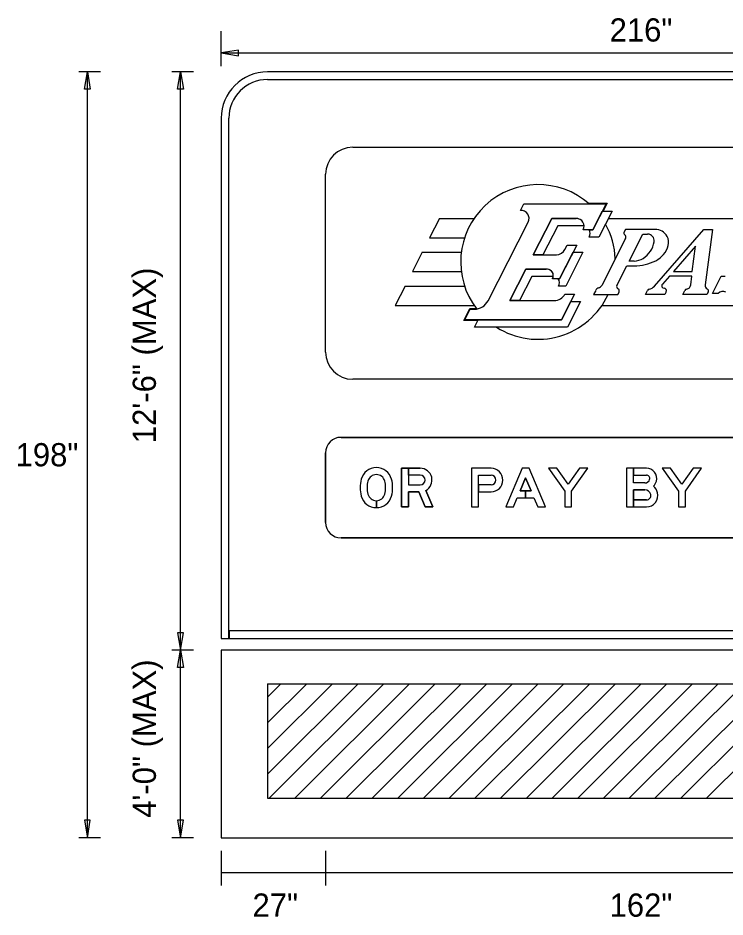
# Model space of a CAD drawing. Extents: x 10268312 to 10268706, y 2142548 to 2142786.
# Drawn here: x 10268663.93 to 10268686.56, y 2142607.93 to 2142636.7 of the extents above; entities that cross this region are included whole.
import ezdxf

# ---------------------------------------------------------------- set-up
doc = ezdxf.new("R2010")
doc.units = 0
for name, color, linetype in [('GSBWFill', 7, 'Continuous'), ('GSDims', 7, 'Continuous'), ('SignPanel', 7, 'Continuous'), ('TextMisc', 7, 'Continuous')]:
    doc.layers.add(name, color=color, linetype=linetype)

msp = doc.modelspace()

# ---------------------------------------------------------------- linework, layer by layer
at = {"layer": 'GSBWFill'}
for p, q in [((10268670.431, 2142635.162), (10268670.431, 2142636.276)), ((10268695.683, 2142634.977), (10268671.916, 2142634.977)), ((10268671.916, 2142634.73), (10268695.683, 2142634.73)), ((10268674.27, 2142623.279), (10268693.329, 2142623.279)), ((10268674.27, 2142623.279), (10268693.329, 2142623.279)), ((10268673.775, 2142620.556), (10268673.775, 2142622.784)), ((10268673.775, 2142620.556), (10268673.775, 2142622.784)), ((10268693.329, 2142620.061), (10268674.27, 2142620.061)), ((10268693.329, 2142620.061), (10268674.27, 2142620.061))]:
    msp.add_line(p, q, dxfattribs=at)
for points in [[(10268670.431, 2142633.492), (10268670.431, 2142616.842), (10268670.678, 2142616.842), (10268670.678, 2142633.492)], [(10268696.921, 2142617.09), (10268670.686, 2142617.09), (10268670.686, 2142616.842), (10268697.169, 2142616.842), (10268697.169, 2142616.842), (10268697.169, 2142633.492)]]:
    msp.add_lwpolyline(points, dxfattribs=at)
for centre, radius, start, end in [((10268671.916, 2142633.492), 1.485, 90, 180), ((10268671.916, 2142633.492), 1.238, 90, 180), ((10268674.27, 2142622.784), 0.495, 90, 180), ((10268674.27, 2142622.784), 0.495, 90, 180), ((10268674.27, 2142620.556), 0.495, 180, 270), ((10268674.27, 2142620.556), 0.495, 180, 270)]:
    msp.add_arc(centre, radius, start, end, dxfattribs=at)
at = {"layer": 'GSDims'}
for p, q in [((10268670.431, 2142635.58), (10268697.169, 2142635.58)), ((10268666.567, 2142634.977), (10268665.871, 2142634.977)), ((10268666.149, 2142610.467), (10268666.149, 2142634.977)), ((10268669.548, 2142634.977), (10268668.852, 2142634.977)), ((10268669.13, 2142616.471), (10268669.13, 2142634.977)), ((10268669.548, 2142616.471), (10268668.852, 2142616.471)), ((10268669.13, 2142610.467), (10268669.13, 2142616.471)), ((10268666.567, 2142610.467), (10268665.871, 2142610.467)), ((10268669.548, 2142610.467), (10268668.852, 2142610.467)), ((10268670.431, 2142610.05), (10268670.431, 2142608.936)), ((10268673.773, 2142610.05), (10268673.773, 2142608.936)), ((10268670.431, 2142609.353), (10268673.773, 2142609.353)), ((10268673.773, 2142609.353), (10268693.826, 2142609.353))]:
    msp.add_line(p, q, dxfattribs=at)
for points in [[(10268670.431, 2142635.58), (10268670.988, 2142635.487), (10268670.988, 2142635.672)], [(10268666.149, 2142634.977), (10268666.242, 2142634.42), (10268666.057, 2142634.42)], [(10268669.13, 2142634.977), (10268669.223, 2142634.42), (10268669.037, 2142634.42)], [(10268669.13, 2142616.471), (10268669.223, 2142617.028), (10268669.037, 2142617.028)], [(10268669.13, 2142616.471), (10268669.223, 2142615.914), (10268669.037, 2142615.914)], [(10268666.149, 2142610.467), (10268666.242, 2142611.024), (10268666.057, 2142611.024)], [(10268669.13, 2142610.467), (10268669.223, 2142611.024), (10268669.037, 2142611.024)]]:
    msp.add_lwpolyline(points, close=True, dxfattribs=at)
at = {"layer": 'SignPanel'}
for p, q in [((10268674.642, 2142632.563), (10268692.958, 2142632.563)), ((10268673.775, 2142626.004), (10268673.775, 2142631.697)), ((10268680.016, 2142630.54), (10268680.122, 2142630.748)), ((10268680.122, 2142630.748), (10268682.752, 2142630.748)), ((10268682.186, 2142630.771), (10268682.789, 2142630.771)), ((10268682.752, 2142630.748), (10268682.33, 2142629.92)), ((10268682.789, 2142630.771), (10268682.659, 2142630.516)), ((10268677.42, 2142630.283), (10268677.105, 2142629.665)), ((10268677.42, 2142630.283), (10268678.53, 2142630.283)), ((10268681.013, 2142630.283), (10268680.422, 2142629.123)), ((10268680.422, 2142629.123), (10268681.013, 2142630.283)), ((10268681.801, 2142630.283), (10268681.013, 2142630.283)), ((10268681.013, 2142630.283), (10268681.801, 2142630.283)), ((10268682.33, 2142629.92), (10268682.633, 2142630.516)), ((10268682.946, 2142630.516), (10268682.524, 2142629.688)), ((10268682.633, 2142630.516), (10268682.946, 2142630.516)), ((10268682.827, 2142630.283), (10268691.652, 2142630.283)), ((10268678.977, 2142627.65), (10268680.261, 2142630.17)), ((10268681.207, 2142630.052), (10268680.734, 2142629.123)), ((10268682.049, 2142630.052), (10268681.207, 2142630.052)), ((10268682.33, 2142629.92), (10268682.021, 2142629.92)), ((10268682.215, 2142629.92), (10268682.33, 2142629.92)), ((10268682.524, 2142629.688), (10268682.215, 2142629.688)), ((10268683.376, 2142629.935), (10268683.334, 2142629.853)), ((10268684.323, 2142629.935), (10268683.376, 2142629.935)), ((10268683.497, 2142628.922), (10268683.935, 2142629.78)), ((10268683.497, 2142628.922), (10268683.935, 2142629.78)), ((10268683.935, 2142629.78), (10268684.084, 2142629.78)), ((10268683.935, 2142629.78), (10268684.084, 2142629.78)), ((10268684.3, 2142628.119), (10268685.879, 2142629.935)), ((10268685.879, 2142629.935), (10268686.158, 2142629.935)), ((10268686.158, 2142629.935), (10268685.926, 2142628.155)), ((10268677.105, 2142629.665), (10268678.225, 2142629.665)), ((10268681.819, 2142629.433), (10268681.267, 2142628.35)), ((10268681.437, 2142629.292), (10268681.509, 2142629.433)), ((10268681.509, 2142629.433), (10268681.819, 2142629.433)), ((10268683.379, 2142629.643), (10268682.613, 2142628.14)), ((10268685.62, 2142629.402), (10268684.914, 2142628.589)), ((10268685.62, 2142629.402), (10268684.914, 2142628.589)), ((10268685.515, 2142628.589), (10268685.62, 2142629.402)), ((10268685.515, 2142628.589), (10268685.62, 2142629.402)), ((10268676.869, 2142629.201), (10268676.554, 2142628.582)), ((10268676.869, 2142629.201), (10268678.12, 2142629.201)), ((10268680.422, 2142629.123), (10268681.162, 2142629.123)), ((10268680.734, 2142629.123), (10268680.422, 2142629.123)), ((10268681.267, 2142628.35), (10268681.7, 2142629.201)), ((10268682.013, 2142629.201), (10268681.461, 2142628.118)), ((10268681.7, 2142629.201), (10268682.013, 2142629.201)), ((10268683.65, 2142628.922), (10268683.497, 2142628.922)), ((10268683.65, 2142628.922), (10268683.497, 2142628.922)), ((10268676.554, 2142628.582), (10268678.12, 2142628.582)), ((10268680.186, 2142628.659), (10268679.673, 2142627.654)), ((10268679.673, 2142627.654), (10268680.186, 2142628.659)), ((10268680.865, 2142628.659), (10268680.186, 2142628.659)), ((10268680.186, 2142628.659), (10268680.835, 2142628.657)), ((10268683.098, 2142628.14), (10268683.418, 2142628.767)), ((10268683.418, 2142628.767), (10268683.65, 2142628.767)), ((10268684.914, 2142628.589), (10268685.515, 2142628.589)), ((10268684.914, 2142628.589), (10268685.515, 2142628.589)), ((10268680.38, 2142628.427), (10268679.986, 2142627.654)), ((10268681.062, 2142628.424), (10268680.38, 2142628.427)), ((10268681.267, 2142628.35), (10268681.034, 2142628.35)), ((10268681.218, 2142628.35), (10268681.267, 2142628.35)), ((10268684.78, 2142628.434), (10268684.556, 2142628.177)), ((10268685.499, 2142628.434), (10268684.78, 2142628.434)), ((10268685.462, 2142628.155), (10268685.499, 2142628.434)), ((10268686.157, 2142627.886), (10268686.437, 2142628.437)), ((10268686.437, 2142628.437), (10268686.562, 2142628.437)), ((10268676.318, 2142628.118), (10268676.003, 2142627.499)), ((10268676.318, 2142628.118), (10268678.225, 2142628.118)), ((10268681.461, 2142628.118), (10268681.229, 2142628.118)), ((10268682.425, 2142627.983), (10268682.355, 2142627.847)), ((10268684.015, 2142627.847), (10268684.082, 2142627.979)), ((10268685.209, 2142627.847), (10268685.277, 2142627.981)), ((10268681.745, 2142627.862), (10268681.324, 2142627.035)), ((10268681.436, 2142627.862), (10268681.745, 2142627.862)), ((10268682.355, 2142627.847), (10268683.129, 2142627.847)), ((10268683.129, 2142627.847), (10268683.17, 2142627.93)), ((10268684.634, 2142627.847), (10268684.015, 2142627.847)), ((10268684.679, 2142627.936), (10268684.634, 2142627.847)), ((10268685.982, 2142627.847), (10268685.209, 2142627.847)), ((10268686.023, 2142627.927), (10268685.982, 2142627.847)), ((10268686.344, 2142627.886), (10268686.157, 2142627.886)), ((10268676.003, 2142627.499), (10268678.53, 2142627.499)), ((10268678.197, 2142627.015), (10268678.393, 2142627.4)), ((10268678.23, 2142627.035), (10268678.406, 2142627.379)), ((10268678.393, 2142627.4), (10268678.535, 2142627.4)), ((10268678.406, 2142627.379), (10268678.535, 2142627.379)), ((10268679.673, 2142627.654), (10268681.093, 2142627.654)), ((10268679.986, 2142627.654), (10268679.673, 2142627.654)), ((10268681.324, 2142627.035), (10268681.627, 2142627.63)), ((10268681.94, 2142627.63), (10268681.518, 2142626.803)), ((10268681.627, 2142627.63), (10268681.94, 2142627.63)), ((10268682.622, 2142627.499), (10268690.233, 2142627.499)), ((10268678.647, 2142627.015), (10268678.197, 2142627.015)), ((10268681.324, 2142627.035), (10268678.23, 2142627.035)), ((10268678.54, 2142626.803), (10268678.658, 2142627.035)), ((10268678.658, 2142627.035), (10268681.324, 2142627.035)), ((10268681.518, 2142626.803), (10268678.54, 2142626.803)), ((10268692.958, 2142625.138), (10268674.642, 2142625.138)), ((10268693.329, 2142623.279), (10268674.27, 2142623.279)), ((10268673.775, 2142622.784), (10268673.775, 2142620.556)), ((10268678.669, 2142622.066), (10268679.071, 2142622.066)), ((10268678.669, 2142622.066), (10268679.071, 2142622.066)), ((10268678.669, 2142622.066), (10268679.071, 2142622.066)), ((10268678.669, 2142621.534), (10268679.071, 2142621.534)), ((10268675.401, 2142621.03), (10268675.401, 2142621.252)), ((10268675.401, 2142621.252), (10268675.401, 2142621.03)), ((10268675.401, 2142621.03), (10268675.401, 2142621.252)), ((10268675.401, 2142621.252), (10268675.401, 2142621.03)), ((10268683.41, 2142621.051), (10268684.047, 2142621.051)), ((10268674.27, 2142620.061), (10268693.324, 2142620.061)), ((10268697.169, 2142616.471), (10268670.431, 2142616.471)), ((10268670.431, 2142616.471), (10268670.431, 2142610.467)), ((10268670.431, 2142610.467), (10268697.169, 2142610.467))]:
    msp.add_line(p, q, dxfattribs=at)
for points in [[(10268676.804, 2142622.289), (10268676.205, 2142622.289), (10268676.205, 2142621.051), (10268676.428, 2142621.051), (10268676.428, 2142621.534), (10268676.756, 2142621.534), (10268676.965, 2142621.051), (10268677.208, 2142621.051), (10268676.98, 2142621.578)], [(10268676.98, 2142621.578), (10268677.208, 2142621.051), (10268676.965, 2142621.051), (10268676.756, 2142621.534), (10268676.428, 2142621.534), (10268676.428, 2142621.051), (10268676.205, 2142621.051), (10268676.205, 2142622.289), (10268676.428, 2142622.289), (10268676.428, 2142621.757), (10268676.804, 2142621.757)], [(10268676.98, 2142621.578), (10268677.208, 2142621.051), (10268676.965, 2142621.051), (10268676.756, 2142621.534), (10268676.428, 2142621.534), (10268676.428, 2142621.051), (10268676.205, 2142621.051), (10268676.205, 2142622.289), (10268676.428, 2142622.289), (10268676.428, 2142621.757), (10268676.804, 2142621.757)], [(10268676.428, 2142622.066), (10268676.428, 2142622.289), (10268676.804, 2142622.289)], [(10268676.428, 2142622.066), (10268676.428, 2142622.289), (10268676.804, 2142622.289)], [(10268679.071, 2142622.289), (10268678.446, 2142622.289), (10268678.446, 2142621.051), (10268678.669, 2142621.051), (10268678.669, 2142621.534)], [(10268679.071, 2142622.289), (10268678.446, 2142622.289), (10268678.446, 2142621.051), (10268678.669, 2142621.051), (10268678.669, 2142622.066)], [(10268679.071, 2142622.289), (10268678.446, 2142622.289), (10268678.446, 2142621.051), (10268678.669, 2142621.051), (10268678.669, 2142622.066)], [(10268684.047, 2142622.289), (10268683.41, 2142622.289), (10268683.41, 2142621.051)], [(10268683.999, 2142621.819), (10268683.632, 2142621.819), (10268683.632, 2142622.289), (10268683.41, 2142622.289), (10268683.41, 2142621.051), (10268683.632, 2142621.051)], [(10268683.999, 2142621.819), (10268683.632, 2142621.819), (10268683.632, 2142622.289), (10268683.41, 2142622.289), (10268683.41, 2142621.051), (10268683.632, 2142621.051)], [(10268684.047, 2142622.289), (10268683.633, 2142622.289), (10268683.633, 2142622.066), (10268684.047, 2142622.066)], [(10268684.047, 2142622.289), (10268683.633, 2142622.289), (10268683.633, 2142622.066), (10268684.047, 2142622.066)], [(10268676.804, 2142622.066), (10268676.428, 2142622.066), (10268676.428, 2142621.757), (10268676.804, 2142621.757)], [(10268676.804, 2142622.066), (10268676.428, 2142622.066)], [(10268676.804, 2142622.066), (10268676.428, 2142622.066)], [(10268679.071, 2142621.757), (10268678.669, 2142621.757), (10268678.669, 2142622.066)], [(10268683.999, 2142621.819), (10268683.632, 2142621.819), (10268683.632, 2142622.066), (10268684.047, 2142622.066)], [(10268679.071, 2142621.757), (10268678.669, 2142621.757), (10268678.669, 2142621.534), (10268679.071, 2142621.534)], [(10268679.071, 2142621.757), (10268678.669, 2142621.757), (10268678.669, 2142621.534), (10268679.071, 2142621.534)], [(10268683.999, 2142621.596), (10268683.632, 2142621.596), (10268683.632, 2142621.274), (10268684.047, 2142621.274)], [(10268683.632, 2142621.051), (10268683.632, 2142621.596), (10268683.999, 2142621.596)], [(10268683.632, 2142621.051), (10268683.632, 2142621.596), (10268683.999, 2142621.596)], [(10268684.047, 2142621.274), (10268683.633, 2142621.274), (10268683.633, 2142621.051), (10268684.047, 2142621.051)], [(10268684.047, 2142621.274), (10268683.633, 2142621.274), (10268683.633, 2142621.051), (10268684.047, 2142621.051)]]:
    msp.add_lwpolyline(points, dxfattribs=at)
for points in [[(10268679.911, 2142621.342), (10268680.446, 2142621.342), (10268680.569, 2142621.051), (10268680.81, 2142621.051), (10268680.29, 2142622.289), (10268680.067, 2142622.289), (10268679.548, 2142621.051), (10268679.789, 2142621.051)], [(10268680.353, 2142621.565), (10268680.179, 2142621.565), (10268680.179, 2142621.342), (10268680.446, 2142621.342), (10268680.569, 2142621.051), (10268680.81, 2142621.051), (10268680.29, 2142622.289), (10268680.067, 2142622.289), (10268679.548, 2142621.051), (10268679.789, 2142621.051), (10268679.911, 2142621.342), (10268680.179, 2142621.342), (10268680.179, 2142621.565), (10268680.005, 2142621.565), (10268680.179, 2142621.979)], [(10268680.353, 2142621.565), (10268680.179, 2142621.565), (10268680.179, 2142621.342), (10268680.446, 2142621.342), (10268680.569, 2142621.051), (10268680.81, 2142621.051), (10268680.29, 2142622.289), (10268680.067, 2142622.289), (10268679.548, 2142621.051), (10268679.789, 2142621.051), (10268679.911, 2142621.342), (10268680.179, 2142621.342), (10268680.179, 2142621.565), (10268680.005, 2142621.565), (10268680.179, 2142621.979)], [(10268681.652, 2142621.553), (10268682.172, 2142622.289), (10268681.899, 2142622.289), (10268681.541, 2142621.781), (10268681.182, 2142622.289), (10268680.909, 2142622.289), (10268681.429, 2142621.553), (10268681.429, 2142621.051), (10268681.652, 2142621.051)], [(10268681.652, 2142621.553), (10268682.172, 2142622.289), (10268681.899, 2142622.289), (10268681.541, 2142621.781), (10268681.182, 2142622.289), (10268680.909, 2142622.289), (10268681.429, 2142621.553), (10268681.429, 2142621.051), (10268681.652, 2142621.051)], [(10268681.652, 2142621.553), (10268682.172, 2142622.289), (10268681.899, 2142622.289), (10268681.541, 2142621.781), (10268681.182, 2142622.289), (10268680.909, 2142622.289), (10268681.429, 2142621.553), (10268681.429, 2142621.051), (10268681.652, 2142621.051)], [(10268685.291, 2142621.553), (10268685.811, 2142622.289), (10268685.538, 2142622.289), (10268685.18, 2142621.781), (10268684.821, 2142622.289), (10268684.549, 2142622.289), (10268685.068, 2142621.553), (10268685.068, 2142621.051), (10268685.291, 2142621.051)], [(10268685.291, 2142621.553), (10268685.811, 2142622.289), (10268685.538, 2142622.289), (10268685.18, 2142621.781), (10268684.821, 2142622.289), (10268684.549, 2142622.289), (10268685.068, 2142621.553), (10268685.068, 2142621.051), (10268685.291, 2142621.051)], [(10268685.291, 2142621.553), (10268685.811, 2142622.289), (10268685.538, 2142622.289), (10268685.18, 2142621.781), (10268684.821, 2142622.289), (10268684.549, 2142622.289), (10268685.068, 2142621.553), (10268685.068, 2142621.051), (10268685.291, 2142621.051)], [(10268680.353, 2142621.565), (10268680.179, 2142621.979), (10268680.005, 2142621.565)]]:
    msp.add_lwpolyline(points, close=True, dxfattribs=at)
for centre, radius, start, end in [((10268674.642, 2142631.697), 0.866, 90, 180), ((10268680.576, 2142628.891), 2.475, 48.5904, 217.4727), ((10268680.033, 2142630.285), 0.255, 332.9998, 93.8045), ((10268681.802, 2142630.036), 0.248, 332.2089, 90), ((10268681.802, 2142630.036), 0.248, 3.5833, 90), ((10268680.576, 2142628.891), 2.475, 2.4236, 29.2771), ((10268681.996, 2142629.804), 0.248, 332.2089, 27.9127), ((10268683.402, 2142629.818), 0.0773, 152.9784, 231.1602), ((10268683.296, 2142629.685), 0.0928, 333.0027, 51.1602), ((10268684.084, 2142629.572), 0.209, 351.076, 90), ((10268684.084, 2142629.572), 0.209, 351.076, 90), ((10268684.323, 2142629.494), 0.441, 29.4315, 90), ((10268684.37, 2142629.521), 0.387, 344.7074, 29.4315), ((10268683.526, 2142629.659), 0.773, 302.4206, 351.076), ((10268683.526, 2142629.659), 0.773, 302.4206, 351.076), ((10268683.997, 2142629.623), 0.773, 296.6431, 344.7074), ((10268681.162, 2142629.432), 0.309, 270, 332.9883), ((10268683.65, 2142629.463), 0.541, 270, 302.4206), ((10268683.65, 2142629.463), 0.541, 270, 302.4206), ((10268683.65, 2142630.314), 1.547, 270, 296.6431), ((10268680.864, 2142628.458), 0.201, 350.3502, 98.3344), ((10268680.864, 2142628.458), 0.201, 327.421, 90), ((10268681.06, 2142628.226), 0.201, 327.421, 37.9799), ((10268682.562, 2142627.913), 0.155, 106.4317, 152.9742), ((10268682.475, 2142628.21), 0.155, 286.4317, 332.9959), ((10268683.167, 2142628.105), 0.0773, 152.9884, 244.7832), ((10268683.101, 2142627.965), 0.0773, 333.0239, 64.7832), ((10268684.151, 2142627.944), 0.0773, 102.7162, 153.0239), ((10268684.066, 2142628.321), 0.309, 282.7162, 318.9966), ((10268684.614, 2142628.126), 0.0773, 138.9824, 268.6869), ((10268684.61, 2142627.971), 0.0773, 332.9784, 88.6869), ((10268685.346, 2142627.946), 0.0773, 99.2397, 153.0239), ((10268685.309, 2142628.175), 0.155, 279.2397, 352.5632), ((10268686.049, 2142628.139), 0.124, 172.5884, 241.8673), ((10268685.954, 2142627.962), 0.0773, 332.9784, 61.8673), ((10268680.576, 2142628.891), 2.475, 237.5383, 335.047), ((10268681.093, 2142628.04), 0.387, 270, 332.5096), ((10268686.493, 2142627.728), 0.217, 64.3795, 133.1892), ((10268678.536, 2142627.874), 0.495, 270, 332.9991), ((10268678.536, 2142627.874), 0.475, 270, 277.5038), ((10268674.642, 2142626.004), 0.866, 180, 270), ((10268674.27, 2142622.784), 0.495, 90, 180), ((10268675.401, 2142621.809), 0.502, 14.9618, 165.0382), ((10268675.401, 2142621.809), 0.502, 14.9618, 165.0382), ((10268675.401, 2142621.809), 0.502, 14.9618, 165.0382), ((10268676.804, 2142621.911), 0.378, 297.837, 90), ((10268676.804, 2142621.911), 0.378, 297.837, 90), ((10268676.804, 2142621.911), 0.378, 297.837, 90), ((10268679.071, 2142621.911), 0.378, 270, 90), ((10268679.071, 2142621.911), 0.378, 270, 90), ((10268679.071, 2142621.911), 0.378, 270, 90), ((10268684.047, 2142621.961), 0.328, 345.5225, 90), ((10268684.047, 2142621.961), 0.328, 345.5225, 90), ((10268684.047, 2142621.961), 0.328, 345.5225, 90), ((10268675.921, 2142621.67), 1.04, 165.0382, 194.9618), ((10268675.921, 2142621.67), 1.04, 165.0382, 194.9618), ((10268675.921, 2142621.67), 1.04, 165.0382, 194.9618), ((10268675.401, 2142621.809), 0.279, 14.9618, 165.0382), ((10268675.401, 2142621.809), 0.279, 14.9618, 165.0382), ((10268675.401, 2142621.809), 0.279, 14.9618, 165.0382), ((10268674.881, 2142621.67), 1.04, 345.0382, 14.9618), ((10268674.881, 2142621.67), 1.04, 345.0382, 14.9618), ((10268674.881, 2142621.67), 1.04, 345.0382, 14.9618), ((10268676.804, 2142621.911), 0.155, 270, 90), ((10268676.804, 2142621.911), 0.155, 270, 90), ((10268676.804, 2142621.911), 0.155, 270, 90), ((10268679.071, 2142621.911), 0.155, 270, 90), ((10268679.071, 2142621.911), 0.155, 270, 90), ((10268679.071, 2142621.911), 0.155, 270, 90), ((10268683.999, 2142621.973), 0.155, 270, 345.5225), ((10268683.999, 2142621.973), 0.155, 270, 345.5225), ((10268683.999, 2142621.973), 0.155, 270, 345.5225), ((10268684.047, 2142621.961), 0.105, 345.5225, 90), ((10268684.047, 2142621.961), 0.105, 345.5225, 90), ((10268684.047, 2142621.961), 0.105, 345.5225, 90), ((10268675.921, 2142621.67), 0.817, 165.0382, 194.9618), ((10268675.921, 2142621.67), 0.817, 165.0382, 194.9618), ((10268675.921, 2142621.67), 0.817, 165.0382, 194.9618), ((10268674.881, 2142621.67), 0.817, 345.0382, 14.9618), ((10268674.881, 2142621.67), 0.817, 345.0382, 14.9618), ((10268674.881, 2142621.67), 0.817, 345.0382, 14.9618), ((10268683.999, 2142621.973), 0.378, 316.7114, 345.5225), ((10268683.999, 2142621.973), 0.378, 316.7114, 345.5225), ((10268683.999, 2142621.973), 0.378, 316.7114, 345.5225), ((10268683.999, 2142621.404), 0.415, 14.4775, 48.4921), ((10268683.999, 2142621.404), 0.415, 14.4775, 48.4921), ((10268683.999, 2142621.404), 0.415, 14.4775, 48.4921), ((10268675.401, 2142621.531), 0.502, 194.9618, 345.0382), ((10268675.401, 2142621.531), 0.502, 194.9618, 270), ((10268675.401, 2142621.531), 0.502, 194.9618, 270), ((10268675.401, 2142621.531), 0.279, 194.9618, 345.0382), ((10268675.401, 2142621.531), 0.279, 194.9618, 270), ((10268675.401, 2142621.531), 0.279, 194.9618, 270), ((10268675.401, 2142621.531), 0.279, 270.0127, 345.0382), ((10268675.401, 2142621.531), 0.279, 270.0127, 345.0382), ((10268675.401, 2142621.531), 0.502, 270.0071, 345.0382), ((10268675.401, 2142621.531), 0.502, 270.0071, 345.0382), ((10268683.999, 2142621.404), 0.192, 14.4775, 90), ((10268683.999, 2142621.404), 0.192, 14.4775, 90), ((10268683.999, 2142621.404), 0.192, 14.4775, 90), ((10268684.047, 2142621.416), 0.365, 270, 14.4775), ((10268684.047, 2142621.416), 0.365, 270, 14.4775), ((10268684.047, 2142621.416), 0.365, 270, 14.4775), ((10268684.047, 2142621.416), 0.142, 270, 14.4775), ((10268684.047, 2142621.416), 0.142, 270, 14.4775), ((10268684.047, 2142621.416), 0.142, 270, 14.4775), ((10268674.27, 2142620.556), 0.495, 180, 270)]:
    msp.add_arc(centre, radius, start, end, dxfattribs=at)
at = {"layer": 'TextMisc'}
for p, q in [((10268671.916, 2142614.965), (10268672.347, 2142615.395)), ((10268671.916, 2142614.143), (10268673.171, 2142615.395)), ((10268671.916, 2142613.321), (10268673.994, 2142615.395)), ((10268671.916, 2142612.5), (10268674.818, 2142615.395)), ((10268671.916, 2142615.395), (10268695.683, 2142615.395)), ((10268671.916, 2142615.395), (10268671.916, 2142611.729)), ((10268671.967, 2142611.729), (10268675.641, 2142615.395)), ((10268672.79, 2142611.729), (10268676.465, 2142615.395)), ((10268673.614, 2142611.729), (10268677.288, 2142615.395)), ((10268674.437, 2142611.729), (10268678.112, 2142615.395)), ((10268675.261, 2142611.729), (10268678.935, 2142615.395)), ((10268676.084, 2142611.729), (10268679.759, 2142615.395)), ((10268676.908, 2142611.729), (10268680.582, 2142615.395)), ((10268677.731, 2142611.729), (10268681.406, 2142615.395)), ((10268678.555, 2142611.729), (10268682.229, 2142615.395)), ((10268679.378, 2142611.729), (10268683.053, 2142615.395)), ((10268680.202, 2142611.729), (10268683.876, 2142615.395)), ((10268681.025, 2142611.729), (10268684.7, 2142615.395)), ((10268681.849, 2142611.729), (10268685.523, 2142615.395)), ((10268682.672, 2142611.729), (10268686.346, 2142615.395)), ((10268683.496, 2142611.729), (10268687.17, 2142615.395)), ((10268684.319, 2142611.729), (10268687.993, 2142615.395)), ((10268685.143, 2142611.729), (10268688.817, 2142615.395)), ((10268685.966, 2142611.729), (10268689.64, 2142615.395)), ((10268671.916, 2142611.729), (10268695.683, 2142611.729))]:
    msp.add_line(p, q, dxfattribs=at)

# ---------------------------------------------------------------- texts
at = {"layer": 'GSDims'}
for s, p in [('216"', (10268682.867, 2142635.945)), ('27"', (10268671.436, 2142607.939)), ('162"', (10268682.867, 2142607.939))]:
    msp.add_text(s, height=0.7427, dxfattribs=at).set_placement(p)
for s, height, rotation, p in [('12\'-6" (MAX)', 0.74272, 90, (10268668.343, 2142623.091)), ('198"', 0.7427, 360, (10268663.852, 2142622.351)), ('4\'-0" (MAX)', 0.74272, 90, (10268668.343, 2142611.103))]:
    msp.add_text(s, height=height, rotation=rotation, dxfattribs=at).set_placement(p)

doc.saveas('drawing.dxf')
